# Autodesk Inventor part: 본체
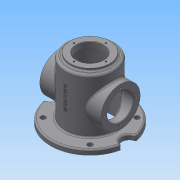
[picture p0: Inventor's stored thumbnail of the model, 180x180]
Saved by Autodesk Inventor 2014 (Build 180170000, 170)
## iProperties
Created: 2018-04
Part Number: 본체
Material: Generic
Document SubType Name: Modeling
Designer: user
Density: 1 g/cm^3
Appearance: Default
Author: user
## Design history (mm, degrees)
sketch "스케치1"
  geometry: L1 (-62, 0)-(62, 0); L2 (-62, 0)-(-62, 27); L3 (-62, 27)-(62, 27); L4 (62, 27)-(62, 0); L5 (-62, 27)-(-62, 40); L6 (-62, 40)-(62, 40); L7 (62, 40)-(62, 27); 2 further points
  constraints: 14 end point, 3 parallel, 3 perpendicular, 1 coincident, 1 horizontal, 1 midpoint
  dimensions: "d0" = 124 distance of L1.start L1.end; "d1" = 54 diameter of L3 L1; "d2" = 80 diameter of L6 L1
revolve "회전1" stored, may be unused: angle "d3" = 90 deg
sketch "스케치3"
  geometry: L1 (0, 65)-(0, -68); L2 (62, 40)-(62, -40) reference; L3 (62, -40)-(-62, -40) reference; L4 (-62, -40)-(-62, 40) reference; L5 (-62, 40)-(62, 40) reference; L6 (0, 65)-(-40, 65); L7 (-40, 65)-(-40, 60); L8 (-40, 60)-(-50, 60); L9 (-50, 60)-(-50, -68); L10 (-50, -68)-(0, -68); L11 (-27, 65)-(-27, 52); L12 (-27, 52)-(-45, 52); L13 (-45, 52)-(-45, -68); 2 further points
  constraints: 18 end point, 4 parallel, 4 perpendicular, 2 point on line, 1 midpoint, 1 vertical, 1 vertical alignment
  dimensions: "d13" = 133 distance of L1.start L1.end; "d14" = 80 diameter of L7 L1; "d15" = 100 diameter of L9 L1; "d16" = 54 diameter of L11 L1; "d17" = 90 diameter of L13 L1; "d18" = 5 distance of L6.end L7.end; "d19" = 13 distance of L11.start L11.end; "d20" = 60 distance from line of L8 point (0, 0)
  node "절단 모서리 투영2"
revolve "회전3" stored, may be unused: angle "d21" = 90 deg
node "작업 평면1"
sketch "스케치4"
  geometry: L1 (0, 0)-(47.73, 47.73); L2 (0, 0)-(67.5, 0); C1 r 50 at (0, 0) reference; C2 r 80 at (0, 0); C3 r 5 at (47.73, 47.73); C4 r 5 at (-47.73, 47.73); C5 r 5 at (-47.73, -47.73); C6 r 5 at (47.73, -47.73); 1 further point
  constraints: 5 centre point, 4 end point, 2 coincident, 1 equal length, 1 horizontal, 9 other
  dimensions: "d23" = 160 diameter of C2; "d25" = 67.5 distance of L1.start L1.end; "d26" = 45 deg angle of L2 L1; "d27" = 10 diameter of C3; "d30" = 360 deg dimension on point (0, 0) C3.centre (derived)
extrude "돌출1" join sketch "스케치4" distance "d32" = 10; taper "d33" = 0 deg
sketch "스케치5"
  geometry: C1 r 50 at (0, 0) reference; C2 r 15 at (-80, 0); C3 r 15 at (80, 0); A1 r 80 centre (0, 0) between (-80, 0) and (80, 0) reference
  constraints: 2 centre point, 2 horizontal alignment, 2 point on circle
  dimensions: "d36" = 30 diameter of C2; "d37" = 30 diameter of C3
extrude "돌출2" cut sketch "스케치5" distance "d38" = 10; taper "d39" = 0 deg
revolve "회전4" stored, may be unused: angle "d40" = 90 deg
revolve "회전5" stored, may be unused: angle "d41" = 90 deg
sketch "스케치6"
  geometry: C1 r 27 at (0, 0) reference; 4 further points
  constraints: 1 vertical alignment, 5 other
  dimensions: "d42" = 32.5 distance of C1.centre point (0, 32.5); "d45" = 360 deg dimension on C1.centre point (0, 32.5) (derived)
hole "구멍1" sketch "스케치6" at (0, 32.5), (-32.5, 0), (0, -32.5), (32.5, 0) diameter "d47" = 3.242; stored, may be unused: countersink angle "d51" = 90 deg, drill point angle "d53" = 118 deg; dims "d48" = 8, "d49" = 4, "d50" = 2, "d52" = 10
sketch "스케치7"
  geometry: C1 r 27 at (0, 0) reference; 4 further points
  constraints: 1 vertical alignment, 5 other
  dimensions: "d54" = 32.5 distance of C1.centre point (0, 32.5); "d57" = 360 deg dimension on C1.centre point (0, 32.5) (derived)
hole "구멍2" sketch "스케치7" at (0, 32.5), (-32.5, 0), (0, -32.5), (32.5, 0) diameter "d59" = 3.242; stored, may be unused: countersink angle "d63" = 90 deg, drill point angle "d65" = 118 deg; dims "d60" = 8, "d61" = 4, "d62" = 2, "d64" = 10
fillet "모깎기1" dims "d66" = 5
fillet "모깎기2" dims "d67" = 3
fillet "모깎기3" dims "d68" = 3
fillet "모깎기4" dims "d69" = 3
fillet "모깎기5" dims "d70" = 3
chamfer "모따기1" distance "d71" = 1; stored, may be unused: second distance "d72" = 2, angle "d73" = 45 deg
node "작업 평면2"
sketch "스케치8"
  geometry: L1 (-77.955, -56)-(77.955, -56) reference; 2 further points
  constraints: 1 vertical alignment, 1 other
  dimensions: "d74" = 70 distance from line of L1 point (0, 14)
feature "엠보싱1" sketch "스케치8" dims "d75" = 0.5, "d76" = 0
node "솔리드1"
mirror "대칭1"
node "절단 모서리 투영3"
